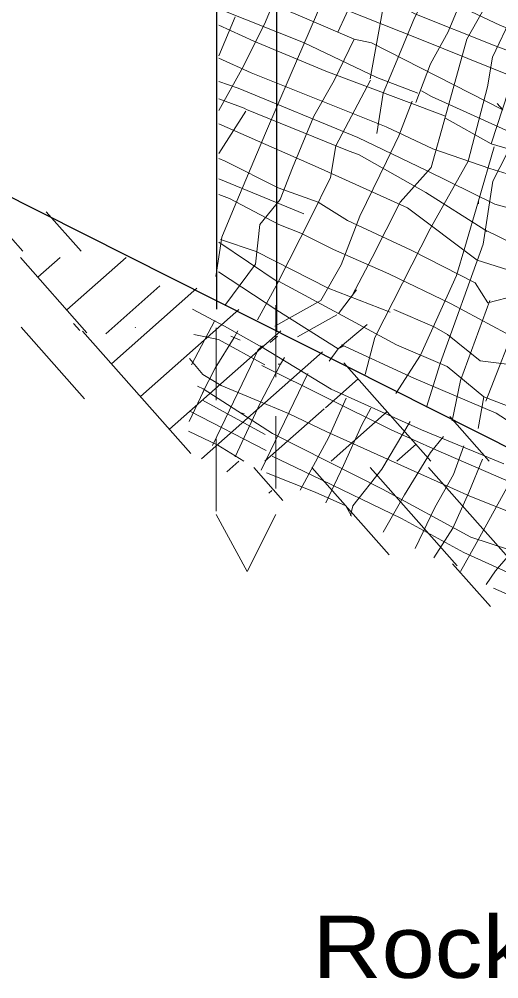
# Model space of a CAD drawing. Extents: x 1083.1 to 1117.1, y 672.5 to 716.5.
# Drawn here: x 1104.323 to 1105.559, y 708.893 to 711.365 of the extents above; entities that cross this region are included whole.
import ezdxf

# ---------------------------------------------------------------- set-up
doc = ezdxf.new("R2010")
doc.units = 0
doc.header["$LTSCALE"] = 0.062
doc.linetypes.add('MEDIUM_DASHED', pattern=[4.5, 3, -1.5])
doc.layers.add('1', color=7, linetype='Continuous', lineweight=13)

msp = doc.modelspace()

# ---------------------------------------------------------------- linework, layer by layer
at = {"layer": '1', "lineweight": 25}
for p, q in [((1104.83175, 711.99533), (1104.83175, 710.61792)), ((1104.98583, 711.99533), (1104.98583, 710.5595)), ((1107.81192, 709.13767), (1103.21475, 711.45358))]:
    msp.add_line(p, q, dxfattribs=at)
at = {"layer": '1'}
for p, q in [((1105.27067, 711.453), (1105.2275, 711.21125)), ((1104.83775, 711.392), (1105.05542, 711.30475)), ((1104.83775, 711.27067), (1104.87925, 711.37108)), ((1104.83775, 711.34983), (1104.92758, 711.308)), ((1105.11275, 711.2315), (1104.92758, 711.308)), ((1105.05542, 711.30475), (1105.24475, 711.21467)), ((1105.47658, 711.31367), (1105.42108, 711.11542)), ((1105.54942, 711.29608), (1105.74025, 711.22525)), ((1104.92067, 711.227), (1104.83775, 711.2645)), ((1104.89658, 711.23625), (1104.83775, 711.13017)), ((1104.83775, 711.20417), (1104.8875, 711.18733)), ((1105.13883, 711.0385), (1105.22825, 711.20792)), ((1105.35025, 711.17408), (1105.24475, 711.21467)), ((1104.8875, 711.18733), (1105.19567, 711.06)), ((1105.35975, 711.18083), (1105.38517, 711.16592)), ((1105.47992, 710.99925), (1105.52983, 711.19117)), ((1104.90258, 711.13592), (1104.83775, 711.15992)), ((1105.24475, 711.07092), (1105.26042, 711.17467)), ((1105.30125, 711.06483), (1105.33542, 711.15367)), ((1104.83775, 711.01892), (1104.90675, 711.12783)), ((1104.9085, 711.13233), (1104.90258, 711.13592)), ((1104.9085, 711.13233), (1105.169, 711.02692)), ((1104.83775, 711.0955), (1105.09317, 710.98283)), ((1105.26892, 710.99883), (1105.30125, 711.06483)), ((1105.13883, 711.0385), (1105.125, 710.9575)), ((1105.38867, 711.03117), (1105.53508, 710.98008)), ((1105.54625, 711.03592), (1105.50658, 710.89692)), ((1104.12042, 711.00708), (1104.33233, 710.76758)), ((1104.85375, 710.99917), (1104.83775, 711.00583)), ((1105.19908, 711.01525), (1105.169, 711.02692)), ((1105.09317, 710.98283), (1105.32308, 710.87867)), ((1105.38183, 710.82467), (1105.47992, 710.99925)), ((1105.53508, 710.98008), (1105.79833, 710.89967)), ((1104.83775, 710.95392), (1105.05608, 710.86375)), ((1104.83775, 710.91383), (1104.86525, 710.90325)), ((1105.0935, 710.89383), (1105.16883, 710.84658)), ((1105.54842, 710.88867), (1105.65442, 710.85833)), ((1104.39308, 710.86875), (1104.48267, 710.76758)), ((1104.87725, 710.88033), (1104.84508, 710.80375)), ((1105.32308, 710.87867), (1105.50308, 710.744)), ((1105.04908, 710.81425), (1105.133, 710.7715)), ((1105.23958, 710.54483), (1105.38183, 710.82467)), ((1104.84508, 710.80375), (1104.82958, 710.70192)), ((1104.99008, 710.68792), (1104.83775, 710.791)), ((1104.84183, 710.79725), (1104.934, 710.767)), ((1105.119, 710.67225), (1104.934, 710.767)), ((1104.32667, 710.75125), (1104.49792, 710.55742)), ((1104.37142, 710.70042), (1104.42883, 710.75133)), ((1104.44592, 710.61625), (1104.59842, 710.75117)), ((1104.93167, 710.73392), (1104.85292, 710.6275)), ((1104.8365, 710.71383), (1104.9865, 710.61517)), ((1104.99008, 710.68792), (1104.93692, 710.59033)), ((1104.54625, 710.55442), (1104.68558, 710.67775)), ((1104.56117, 710.47742), (1104.78108, 710.67192)), ((1105.119, 710.67225), (1105.27875, 710.61075)), ((1105.14583, 710.60708), (1105.19225, 710.668)), ((1105.09983, 710.64042), (1104.98158, 710.57442)), ((1105.45975, 710.43458), (1105.53575, 710.64)), ((1104.63567, 710.39317), (1104.88917, 710.61708)), ((1104.85208, 710.57392), (1104.76983, 710.618)), ((1105.39208, 710.57242), (1105.28833, 710.61758)), ((1105.61758, 710.61892), (1105.52475, 710.38133)), ((1104.82708, 710.58858), (1104.76742, 710.47508)), ((1105.14108, 710.60333), (1105.03992, 710.54667)), ((1104.328, 710.57133), (1104.49125, 710.38683)), ((1104.463, 710.58117), (1104.47925, 710.56283)), ((1104.48667, 710.56158), (1104.7655, 710.2465)), ((1104.62208, 710.57133), (1104.62317, 710.57)), ((1104.71017, 710.309), (1104.99692, 710.56242)), ((1104.85208, 710.57392), (1104.94242, 710.52392)), ((1104.87667, 710.54483), (1104.88667, 710.56233)), ((1105.21958, 710.57858), (1105.14467, 710.51592)), ((1104.83675, 710.53983), (1104.773, 710.55258)), ((1104.82783, 710.46575), (1104.87667, 710.54483)), ((1104.95592, 710.47508), (1104.83675, 710.53983)), ((1104.86875, 710.54892), (1104.89225, 710.53842)), ((1104.9695, 710.53208), (1104.98825, 710.54867)), ((1105.23958, 710.54483), (1105.21442, 710.44967)), ((1104.919, 710.47033), (1104.938, 710.51258)), ((1104.938, 710.51258), (1104.95008, 710.524)), ((1105.14467, 710.51592), (1105.122, 710.48433)), ((1104.7965, 710.45017), (1104.76158, 710.49058)), ((1104.79317, 710.23233), (1105.10475, 710.50775)), ((1104.99592, 710.476), (1105.00667, 710.49358)), ((1105.35708, 710.49958), (1105.29333, 710.40042)), ((1104.82783, 710.46575), (1104.79583, 710.40242)), ((1104.82133, 710.26717), (1104.919, 710.47033)), ((1105.28142, 710.30758), (1104.94867, 710.47317)), ((1105.15975, 710.47983), (1105.38383, 710.2265)), ((1105.40725, 710.47775), (1105.37267, 710.36542)), ((1105.64267, 710.46817), (1105.51067, 710.48492)), ((1104.7965, 710.45017), (1104.84333, 710.42133)), ((1104.94633, 710.20367), (1105.06667, 710.45217)), ((1105.112, 710.364), (1105.19625, 710.4385)), ((1104.78275, 710.41958), (1104.79692, 710.41275)), ((1104.79692, 710.41275), (1104.976, 710.29758)), ((1104.84333, 710.42133), (1105.01692, 710.3495)), ((1105.45975, 710.43458), (1105.43808, 710.33042)), ((1104.761, 710.32875), (1104.79842, 710.40683)), ((1105.12075, 710.28875), (1105.16575, 710.389)), ((1105.52008, 710.39242), (1105.50575, 710.31075)), ((1104.95725, 710.29542), (1104.79533, 710.38408)), ((1104.8795, 710.23767), (1104.944, 710.37625)), ((1104.76242, 710.35558), (1104.95942, 710.25417)), ((1104.893, 710.35083), (1104.90283, 710.349)), ((1104.95625, 710.2265), (1105.10858, 710.36125)), ((1105.11592, 710.30167), (1105.01692, 710.3495)), ((1105.1265, 710.2265), (1105.271, 710.35433)), ((1105.43208, 710.34158), (1105.534, 710.2265)), ((1104.75958, 710.3035), (1104.835, 710.26733)), ((1105.04733, 710.15225), (1105.12075, 710.28875)), ((1105.28142, 710.30758), (1105.39633, 710.256)), ((1105.3825, 710.24883), (1105.4165, 710.28983)), ((1104.835, 710.26733), (1104.90217, 710.22617)), ((1105.29617, 710.2265), (1105.3455, 710.27008)), ((1104.97467, 710.23942), (1105.07683, 710.19083)), ((1105.31575, 710.13975), (1105.3825, 710.24883)), ((1105.57708, 710.1775), (1105.39633, 710.256)), ((1104.85817, 710.19908), (1104.88917, 710.2265)), ((1105.11267, 710.119), (1105.15867, 710.21558)), ((1104.92725, 710.21025), (1105.0025, 710.12525)), ((1104.96025, 710.19658), (1105.08533, 710.14692)), ((1105.07708, 710.21033), (1105.27642, 709.98508)), ((1105.22733, 710.21042), (1105.45125, 709.95733)), ((1105.37792, 710.2105), (1105.59033, 709.97008)), ((1104.966, 710.14392), (1104.974, 710.15092)), ((1105.08533, 710.14692), (1105.16492, 710.11117)), ((1105.26092, 710.04358), (1105.31575, 710.13975)), ((1105.48417, 710.13625), (1105.81425, 710.00408)), ((1105.16492, 710.11117), (1105.17925, 710.08508)), ((1105.18258, 710.11125), (1105.17675, 710.08642)), ((1105.34292, 710.00175), (1105.39342, 710.1075)), ((1105.54992, 709.94367), (1105.67008, 710.08492)), ((1105.39108, 709.97725), (1105.44042, 710.05433)), ((1105.46033, 709.94208), (1105.50017, 710.01417)), ((1105.43917, 709.96225), (1105.53683, 709.85183)), ((1105.54992, 709.94367), (1105.52625, 709.90858)), ((1105.54492, 709.89908), (1105.63908, 709.85817))]:
    msp.add_line(p, q, dxfattribs=at)
at = {"layer": '1', "linetype": 'MEDIUM_DASHED'}
for p, q in [((1104.98458, 710.6285), (1104.98458, 710.081)), ((1104.83058, 710.57008), (1104.83058, 710.098)), ((1104.83058, 710.08892), (1104.91075, 709.94192)), ((1104.91075, 709.94192), (1104.98458, 710.08892))]:
    msp.add_line(p, q, dxfattribs=at)
at = {"layer": '1'}
for points in [[(1104.89658, 711.23625), (1104.95508, 711.35233), (1105.00717, 711.47867), (1105.13625, 711.78708)], [(1104.87725, 710.88033), (1104.95775, 711.07158), (1105.02158, 711.2195), (1105.089, 711.37658), (1105.12233, 711.46308), (1105.19917, 711.62692), (1105.23867, 711.72942)], [(1105.14442, 711.33175), (1105.18725, 711.425), (1105.24108, 711.55592), (1105.28225, 711.66292), (1105.30283, 711.70733)], [(1105.3445, 711.15017), (1105.383, 711.25033), (1105.42842, 711.33225), (1105.48133, 711.46083), (1105.52542, 711.54842), (1105.5475, 711.62358)], [(1105.26042, 711.17467), (1105.29675, 711.26), (1105.34183, 711.36817), (1105.40208, 711.48875), (1105.46275, 711.60133)], [(1104.915, 711.58992), (1105.01525, 711.53567), (1105.17158, 711.48333), (1105.253, 711.452), (1105.27442, 711.41767), (1105.34233, 711.37842), (1105.54942, 711.29608)], [(1105.47658, 711.31367), (1105.53117, 711.41033), (1105.56708, 711.50367), (1105.59733, 711.59133)], [(1105.52983, 711.19117), (1105.54192, 711.26758), (1105.59308, 711.37342), (1105.66383, 711.52133), (1105.67492, 711.57717)], [(1105.16067, 711.52675), (1105.39717, 711.42767), (1105.56275, 711.34858), (1105.79917, 711.25675)], [(1105.66408, 711.18925), (1105.35533, 711.31325), (1105.0195, 711.44775)], [(1105.18575, 711.31317), (1105.07592, 711.36067), (1104.95108, 711.414)], [(1104.93167, 710.73392), (1104.94342, 710.83658), (1104.99558, 710.90017), (1105.02717, 710.98208), (1105.08183, 711.11533), (1105.13458, 711.20742), (1105.18575, 711.31317), (1105.23058, 711.30375)], [(1105.23058, 711.30375), (1105.56925, 711.13158), (1105.55467, 711.14767)], [(1105.38867, 711.03117), (1105.26858, 711.08783), (1104.92067, 711.227)], [(1105.18108, 710.65367), (1105.2325, 710.75142), (1105.30458, 710.89367), (1105.38408, 710.98333), (1105.42108, 711.11542), (1105.11275, 711.2315)], [(1105.59825, 711.225), (1105.53892, 711.04392), (1105.41933, 711.11092)], [(1105.40725, 710.47775), (1105.51858, 710.78517), (1105.54325, 710.94817), (1105.66858, 711.19275)], [(1105.38517, 711.16592), (1105.57658, 711.079), (1105.78392, 711.01842), (1105.91717, 710.96633)], [(1105.19567, 711.06), (1105.37242, 710.97567), (1105.54842, 710.88867)], [(1105.53892, 711.04392), (1105.735, 710.98675), (1105.73142, 710.9945)], [(1105.19908, 711.01525), (1105.37075, 710.91883), (1105.523, 710.82267), (1105.52808, 710.81808)], [(1105.0935, 710.89383), (1104.99017, 710.931), (1104.85375, 710.99917)], [(1105.09983, 710.64042), (1105.15258, 710.73258), (1105.20075, 710.85775), (1105.26892, 710.99883)], [(1105.77692, 710.25958), (1105.6165, 710.35533), (1105.52008, 710.39242), (1105.42558, 710.47067), (1105.29467, 710.52625), (1105.14583, 710.60708), (1104.99092, 710.69017), (1105.07475, 710.854), (1105.125, 710.9575)], [(1104.86525, 710.90325), (1104.99175, 710.83625), (1105.04908, 710.81425)], [(1105.47092, 710.77733), (1105.50658, 710.89692), (1105.50633, 710.88908)], [(1105.16883, 710.84658), (1105.33317, 710.77025), (1105.498, 710.68583), (1105.53008, 710.63433), (1105.60317, 710.65325), (1105.62192, 710.61208), (1105.71533, 710.57608)], [(1105.523, 710.82267), (1105.64217, 710.76367), (1105.72742, 710.7335)], [(1105.133, 710.7715), (1105.275, 710.70892), (1105.43558, 710.6315), (1105.6825, 710.49983)], [(1105.35708, 710.49958), (1105.44975, 710.70442), (1105.47092, 710.77733)], [(1105.50308, 710.744), (1105.61425, 710.70908), (1105.73392, 710.66042)], [(1104.9865, 710.61517), (1105.14467, 710.51592), (1105.159, 710.52242)], [(1105.51067, 710.48492), (1105.42608, 710.553), (1105.39208, 710.57242)], [(1104.94308, 710.52375), (1105.1265, 710.41192), (1105.35925, 710.30733), (1105.5715, 710.22008)], [(1105.15367, 710.52625), (1105.33992, 710.44058), (1105.552, 710.35), (1105.75025, 710.22233), (1105.89333, 710.1495), (1106.114, 710.05575)], [(1104.944, 710.37625), (1104.99592, 710.476), (1104.99033, 710.47608)], [(1105.15867, 710.21558), (1105.20567, 710.32017), (1105.22867, 710.36342)], [(1105.18258, 710.11125), (1105.25717, 710.20617), (1105.32992, 710.32867)], [(1106.48183, 709.51175), (1106.32475, 709.57958), (1106.2355, 709.63308), (1105.97925, 709.76425), (1105.64083, 709.98042), (1105.4865, 710.031), (1105.25875, 710.15458), (1104.976, 710.29758)], [(1105.11592, 710.30167), (1105.3575, 710.19317), (1105.48417, 710.13625)], [(1105.39342, 710.1075), (1105.44217, 710.19258), (1105.46833, 710.26642)], [(1105.44042, 710.05433), (1105.48133, 710.14558), (1105.51633, 710.2315)], [(1105.07683, 710.19083), (1105.30758, 710.079), (1105.46858, 709.991), (1105.69958, 709.88633)], [(1105.50017, 710.01417), (1105.57892, 710.15792), (1105.59308, 710.21308)]]:
    msp.add_lwpolyline(points, dxfattribs=at)

# ---------------------------------------------------------------- texts
at = {"layer": '1', "width": 1.15}
msp.add_text('Rock', height=0.16, dxfattribs=at).set_placement((1105.079, 708.89542))

doc.saveas('drawing.dxf')
